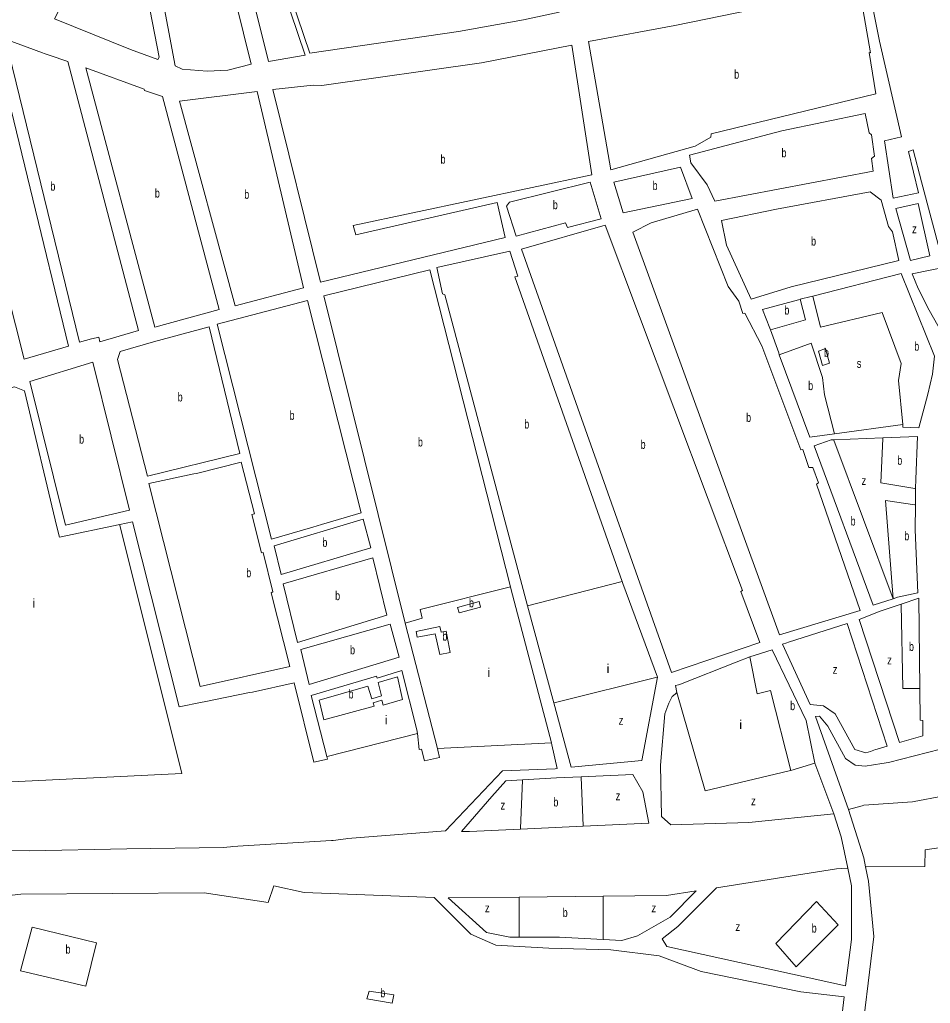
# Model space of a CAD drawing. Extents: x 639657 to 671642, y 222838 to 252123.
# Drawn here: x 642652 to 643678, y 234105 to 235214 of the extents above; entities that cross this region are included whole.
import ezdxf

# ---------------------------------------------------------------- set-up
doc = ezdxf.new("R2010")
doc.units = 0
doc.header["$LTSCALE"] = 4
doc.layers.add('1', color=7, linetype='Continuous', lineweight=13)
doc.layers.add('21', color=7, linetype='Continuous', lineweight=13)
doc.layers.add('7', color=7, linetype='Continuous')

msp = doc.modelspace()

# ---------------------------------------------------------------- linework, layer by layer
at = {"layer": '1'}
for p, q in [((642679.704, 235175.925), (642684.992, 235173.91)), ((643570.344, 234747.002), (643647.326, 234757.379)), ((642848.234, 234702.053), (642851.383, 234702.468)), ((642703.569, 234644.238), (642775.692, 234660.994)), ((642693.955, 234642.004), (642696.839, 234630.37)), ((642778.965, 234647.769), (642831.634, 234439.38)), ((643598.221, 234537.798), (643643.569, 234398.913)), ((643122.747, 234392.465), (643086.25, 234533.693)), ((643518.463, 234512.101), (643584.495, 234533.351)), ((643584.495, 234533.351), (643629.7, 234394.906)), ((643474.826, 234495.531), (643459.398, 234489.597)), ((642855.386, 234462.023), (642956.465, 234484.706)), ((643396.673, 234464.64), (643459.398, 234489.597)), ((642961.146, 234466.215), (642914.438, 234455.926)), ((642910.883, 234455.51), (642859.705, 234444.903)), ((642914.438, 234455.926), (642910.883, 234455.51)), ((643549.039, 234428.282), (643586.076, 234323.444)), ((642998.733, 234380.437), (642998.014, 234383.269)), ((643616.384, 234391.059), (643611.106, 234388.81)), ((643631.069, 234376.7), (643689.772, 234391.725)), ((643108.179, 234378.384), (643125.147, 234382.28)), ((643548.162, 234375.637), (643569.516, 234318.834)), ((643631.069, 234376.7), (643623.852, 234375.548)), ((643131.869, 234299.316), (643021.494, 234290.942)), ((643573.35, 234047.549), (643581.367, 234112.236))]:
    msp.add_line(p, q, dxfattribs=at)
for points in [[(642792.992, 235344.19), (642803.085, 235372.547), (642812.184, 235391.358), (642822.52, 235402.861), (642851.453, 235411.575), (642912.886, 235163.607), (642886.488, 235156.829), (642863.327, 235155.95), (642835.079, 235158.203), (642827.248, 235161.734)], [(642873.517, 235403.517), (642899.409, 235409.278), (642902.966, 235408.882), (642910.604, 235400.985), (642915.534, 235378.154), (642913.124, 235365.76), (642915.814, 235345.055), (642973.841, 235173.995), (642932.486, 235166.609)], [(642709.599, 235251.146), (642717.937, 235248.023), (642722.598, 235253.215), (642743.824, 235299.576), (642759.405, 235327.238), (642772.163, 235345.145), (642775.311, 235345.865), (642809.04, 235171.529), (642807.523, 235168.986), (642776.917, 235180.371), (642691.195, 235214.845)], [(642958.021, 235238.366), (643232.017, 235323.842), (643237.323, 235313.704), (643260.09, 235222.492), (643219.779, 235213.541), (643146.663, 235200.535), (642978.891, 235176.186)], [(643292.982, 235189.183), (643390.264, 235207.133), (643598.223, 235250.179), (643610.993, 235176.605), (643609.265, 235176.701), (643617.095, 235130.323), (643431.389, 235085.108), (643431.093, 235081.554), (643413.44, 235071.451), (643318.311, 235044.471)], [(642620.111, 235201.947), (642706.889, 234845.717), (642657.042, 234831.154), (642560.042, 235213.753), (642561.248, 235219.645)], [(642937.233, 235135.046), (642982.632, 235140.052), (642992.386, 235139.572), (643172.651, 235165.277), (643274.197, 235185.169), (643296.685, 235039.026), (643027.906, 234981.69), (643030.673, 234971.443), (643190.188, 235007.952), (643199.017, 234968.38), (642990.872, 234918.023)], [(642726.475, 235159.41), (642792.362, 235135.64), (642792.772, 235133.915), (642812.903, 235127.171), (642876.959, 234887.028), (642804.164, 234867.322)], [(642832.217, 235122.049), (642919.459, 235132.862), (642971.788, 234911.469), (642894.829, 234891.141)], [(643407.064, 235061.076), (643510.826, 235088.487), (643604.854, 235108.154), (643609.273, 235086.337), (643612.123, 235084.213), (643615.329, 235060.057), (643611.881, 235057.306), (643613.946, 235043.097), (643435.325, 235009.376), (643426.952, 235027.831), (643408.607, 235052.552)], [(643321.594, 235030.672), (643396.732, 235047.745), (643409.819, 235012.449), (643332.241, 234995.978)], [(643200.561, 235003.515), (643204.207, 235008.094), (643295.079, 235030.696), (643307.265, 234989.408), (643269.496, 234979.55), (643267.298, 234984.849), (643211.51, 234969.736)], [(643442.996, 234987.569), (643505.14, 235000.238), (643610.547, 235019.633), (643623.064, 235010.532), (643631.261, 234980.806), (643635.846, 234974.728), (643642.931, 234942.562), (643521.599, 234912.562), (643476.423, 234898.825), (643448.445, 234959.765)], [(643639.438, 235001.064), (643664.807, 235006.502), (643677.962, 234947.715), (643656.037, 234942.451)], [(643343.06, 234974.485), (643363.862, 234984.8), (643415.841, 235000.385), (643450.586, 234913.167), (643462.409, 234896.449), (643467.114, 234882.755), (643469.45, 234883.067), (643488.433, 234846.164), (643532.39, 234729.123), (643534.523, 234729.332), (643541.276, 234708.944), (643545.949, 234708.957), (643552.492, 234691.614), (643550.158, 234690.389), (643599.357, 234547.777), (643508.191, 234520.605)], [(643217.437, 234955.031), (643311.752, 234982.212), (643466.524, 234570.235), (643464.901, 234569.316), (643486.268, 234511.606), (643386.584, 234477.912)], [(642987.237, 234643.366), (642982.237, 234641.901), (642935.775, 234628.29), (642874.643, 234870.745), (642976.291, 234897.369), (643036.993, 234658.029), (642992.237, 234644.722)], [(642765.318, 234839.998), (642802.577, 234850.869), (642865.321, 234867.601), (642900.094, 234724.846), (642795.819, 234699.463), (642762.089, 234830.749)], [(642938.638, 234620.582), (643039.245, 234650.725), (643047.752, 234618.463), (642946.535, 234588.622)], [(642948.795, 234577.967), (643049.912, 234607.199), (643065.912, 234542.467), (642964.899, 234511.916)], [(642968.677, 234503.805), (643069.49, 234532.629), (643079.636, 234495.091), (642978.319, 234464.336)], [(642989.637, 234446.702), (643044.357, 234462.701), (643048.963, 234448.195), (643059.724, 234451.577), (643055.947, 234466.569), (643077.655, 234472.951), (643083.607, 234447.484), (643061.779, 234441.328), (643060.039, 234446.907), (643050.434, 234443.917), (643051.407, 234439.872), (642994.87, 234424.482)]]:
    msp.add_lwpolyline(points, close=True, dxfattribs=at)
for points in [[(643668.427, 235031.072), (643658.895, 235067.19), (643653.922, 235065.145), (643665.002, 235018.777), (643636.57, 235012.703), (643626.565, 235077.452), (643645.755, 235081.874), (643621.121, 235189.732), (643609.196, 235250.008)], [(642734.807, 234854.53), (642732.807, 234853.975), (642719.273, 234850.22), (642635.982, 235192.043), (642677.704, 235176.662), (642679.704, 235175.925)], [(642684.992, 235173.91), (642706.241, 235166.661), (642785.987, 234863.614), (642742.434, 234850.897), (642741.159, 234855.799)], [(643759.519, 235053.001), (643754.458, 234994.974), (643750.463, 234965.72), (643690.055, 234948.995), (643668.427, 235031.072)], [(643331.18, 234580.4), (643209.89, 234923.838), (643213.342, 234924.762), (643204.438, 234952.962), (643122.293, 234934.549), (643128.356, 234904.919), (643131, 234903.708), (643224.471, 234553.082)], [(643825.915, 234873.936), (643823.915, 234873.513), (643819.661, 234872.613), (643807.456, 234922.227), (643750.58, 234915.36), (643731.775, 234920.078), (643739.344, 234941.726), (643735.175, 234943.136), (643657.791, 234927.535), (643664.807, 234910.864), (643677.085, 234886.296), (643699.887, 234845.935), (643717.057, 234827.982)], [(643205.017, 234574.55), (643114.071, 234931.784), (642994.667, 234902.601), (643086.25, 234533.693)], [(643546.006, 234902.175), (643645.404, 234927.847), (643682.906, 234834.648), (643680.718, 234814.436), (643675.692, 234791.678), (643665.52, 234753.675), (643647.435, 234754.435), (643647.326, 234757.379)], [(643498.245, 234864.265), (643497.469, 234866.265), (643489.353, 234887.186), (643529.768, 234898.137), (643531.768, 234898.679)], [(643531.768, 234898.679), (643544.006, 234901.684), (643546.006, 234902.175)], [(643508.165, 234836.17), (643507.459, 234838.17), (643498.245, 234864.265)], [(642741.159, 234855.799), (642739.508, 234855.469), (642734.807, 234854.53)], [(642775.692, 234660.994), (642734.26, 234827.622), (642663.4, 234805.891), (642703.569, 234644.238)], [(643570.344, 234747.002), (643542.415, 234743.367), (643508.165, 234836.17)], [(642589.085, 234784.149), (642646.244, 234800.155), (642657.329, 234795.415), (642693.955, 234642.004)], [(645027.741, 234783.832), (644647.049, 234601.79), (644568.712, 234562.654), (644534.803, 234547.02), (644287.268, 234440.965), (643791.734, 234295.819), (643672.568, 234278.225), (643672.232, 234259.476), (643605.918, 234259.012), (643605.418, 234259.008)], [(643547.517, 234733.533), (643566.499, 234740.289), (643569.482, 234740.397), (643624.688, 234742.399)], [(643624.688, 234742.399), (643663.917, 234743.822), (643661.895, 234696.095), (643661.768, 234685.434), (643661.547, 234666.827)], [(643636.34, 234561.096), (643613.769, 234553.809), (643547.517, 234733.533)], [(642851.383, 234702.468), (642901.743, 234714.9), (642916.609, 234656.866), (642913.462, 234656.045), (642924.331, 234612.925), (642926.464, 234613.236), (642937.438, 234568.898), (642935.409, 234567.877), (642956.465, 234484.706)], [(642855.386, 234462.023), (642797.668, 234690.838), (642848.234, 234702.053)], [(643661.547, 234666.827), (643661.216, 234638.93), (643664.227, 234567.866), (643641.381, 234562.723), (643636.34, 234561.096)], [(642696.839, 234630.37), (642764.631, 234644.732), (642778.965, 234647.769)], [(643205.017, 234574.55), (643205.545, 234572.55), (643251.449, 234398.526)], [(643331.18, 234580.4), (643331.918, 234578.4), (643370.849, 234472.891)], [(643645.468, 234555.037), (643665.257, 234561.878), (643666.626, 234459.869)], [(643370.849, 234472.891), (643353.189, 234378.718), (643273.355, 234371.378), (643253.858, 234443.848), (643224.471, 234553.082)], [(643598.221, 234537.798), (643622.014, 234546.929), (643645.468, 234555.037)], [(643542.941, 234441.937), (643511.67, 234510.056), (643516.463, 234511.499), (643518.463, 234512.101)], [(643474.826, 234495.531), (643500.002, 234503.523), (643538.59, 234423.932), (643548.162, 234375.637)], [(642998.014, 234383.269), (642980.583, 234451.956), (643053.983, 234473.796), (643054.902, 234471.768), (643082.82, 234480.277), (643099.637, 234413.314)], [(642998.733, 234380.437), (642983.378, 234376.859), (642961.146, 234466.215)], [(643392.63, 234455.389), (643391.131, 234463.213), (643394.673, 234464.125), (643396.673, 234464.64)], [(643392.63, 234455.389), (643390.63, 234453.65), (643387.358, 234450.805), (643383.515, 234443.483), (643379.175, 234431.286), (643374.332, 234373.601)], [(643666.626, 234459.869), (643667.102, 234424.408), (643669.744, 234423.908), (643669.988, 234406.546), (643643.569, 234398.913)], [(642859.705, 234444.903), (642857.705, 234444.509), (642831.634, 234439.38)], [(643611.106, 234388.81), (643605.522, 234387.271), (643593.12, 234390.991), (643571.183, 234431.236), (643557.809, 234440.566), (643542.941, 234441.937)], [(643593.567, 234373.427), (643582.678, 234381.214), (643562.987, 234417.404), (643553.489, 234428.605), (643549.039, 234428.282)], [(643108.179, 234378.384), (643104.767, 234391.601), (643102.33, 234391.086), (643100.143, 234409.135), (643099.637, 234413.314)], [(643251.449, 234398.526), (643251.875, 234396.526), (643257.612, 234369.607)], [(643629.7, 234394.906), (643618.384, 234391.637), (643616.384, 234391.059)], [(643122.747, 234392.465), (643123.218, 234390.465), (643125.147, 234382.28)], [(643374.332, 234373.601), (643375.381, 234315.832), (643385.766, 234306.42), (643473.636, 234309.011), (643569.516, 234318.834)], [(643623.852, 234375.548), (643605.049, 234372.547), (643593.567, 234373.427)], [(643131.869, 234299.316), (643196.054, 234367.194), (643255.612, 234369.529), (643257.612, 234369.607)], [(643218.639, 234357.045), (643256.997, 234359.406), (643284.685, 234360.537)], [(643284.685, 234360.537), (643342.943, 234362.916), (643354.344, 234343.613), (643361.251, 234308.073)], [(643216.324, 234301.483), (643158.772, 234298.865), (643150.002, 234298.865), (643184.205, 234338.348), (643199.991, 234355.897), (643218.639, 234357.045)], [(643660.104, 234332.5), (643692.02, 234338.612), (643694.02, 234338.995)], [(643586.076, 234323.444), (643601.425, 234327.717), (643603.425, 234328.274)], [(643603.425, 234328.274), (643658.104, 234332.351), (643660.104, 234332.5)], [(643585.296, 234257.257), (643577.981, 234292.723), (643569.516, 234318.834)], [(643586.076, 234323.444), (643603.414, 234269.032), (643605.418, 234259.008)], [(643361.251, 234308.073), (643287.011, 234304.697), (643216.324, 234301.483)], [(642891.599, 234281.802), (643003.347, 234288.441), (643005.347, 234288.56)], [(643021.494, 234290.942), (643019.494, 234290.647), (643005.347, 234288.56)], [(642881.423, 234280.787), (642772.52, 234279.353), (642662.503, 234276.799), (642591.792, 234278.015), (642391.857, 234279.058), (642034.894, 234276.516)], [(642881.423, 234280.787), (642889.599, 234281.603), (642891.599, 234281.802)], [(643585.296, 234257.257), (643584.796, 234257.226), (643572.505, 234256.476), (643437.364, 234235.396)], [(643582.906, 234124.647), (643589.382, 234176.904), (643589.382, 234237.445), (643585.296, 234257.257)], [(643605.418, 234259.008), (643608.676, 234242.71), (643614.815, 234180.413), (643598.392, 234047.419)], [(643119.12, 234224.471), (642972.745, 234230.146), (642938.301, 234237.503), (642932.19, 234218.865), (642859.711, 234229.772), (642653.107, 234227.915), (642617.407, 234224.107), (642056.301, 234221.39), (642032.886, 234208.556), (642007.734, 234217.783), (641601.897, 234217.647)], [(643414.508, 234231.832), (643380.893, 234226.588), (643309.617, 234225.809), (643214.9, 234224.773), (643134.874, 234223.898)], [(643309.617, 234177.08), (643330.665, 234176.027), (643348.205, 234181.291), (643385.039, 234202.349), (643414.508, 234231.832)], [(643437.364, 234235.396), (643393.809, 234191.82), (643376.269, 234177.781), (643381.531, 234169.007), (643582.906, 234124.647)], [(643581.367, 234112.236), (643532.376, 234118.117), (643420.119, 234140.93), (643372.761, 234158.478), (643318.387, 234165.498), (643248.226, 234167.253), (643188.59, 234170.762), (643160.526, 234183.046), (643119.12, 234224.471)], [(643134.874, 234223.898), (643178.066, 234184.801), (643204.376, 234179.536), (643214.9, 234179.536)], [(643214.9, 234179.536), (643260.504, 234179.536), (643309.617, 234177.08)]]:
    msp.add_lwpolyline(points, dxfattribs=at)
at = {"layer": '21'}
for p, q in [((643224.471, 234553.082), (643331.18, 234580.4)), ((643424.484, 234344.607), (643392.63, 234455.389)), ((643251.449, 234398.526), (643122.747, 234392.465)), ((643548.162, 234375.637), (643521.146, 234367.632))]:
    msp.add_line(p, q, dxfattribs=at)
for points in [[(643498.245, 234864.265), (643537.636, 234875.549), (643531.768, 234898.679)], [(643647.326, 234757.379), (643642.435, 234807.014), (643645.438, 234826.416), (643624.173, 234883.619), (643554.621, 234867.374), (643546.006, 234902.175)], [(643508.165, 234836.17), (643543.996, 234849.27), (643556.684, 234810.521), (643559.168, 234791.034), (643570.344, 234747.002)], [(643569.482, 234740.397), (643569.668, 234739.897), (643636.34, 234561.096)], [(643661.768, 234685.434), (643660.946, 234685.571), (643622.71, 234691.947), (643624.668, 234741.899), (643624.688, 234742.399)], [(643636.34, 234561.096), (643627.972, 234671.767), (643661.047, 234666.901), (643661.547, 234666.827)], [(642764.631, 234644.732), (642764.756, 234644.232), (642834.724, 234364.233), (642611.792, 234353.353), (642611.292, 234353.329)], [(643086.25, 234533.693), (643105.641, 234539.232), (643103.486, 234548.872), (643205.017, 234574.55)], [(643645.468, 234555.037), (643645.477, 234554.537), (643647.263, 234459.869), (643666.126, 234459.869), (643666.626, 234459.869)], [(643521.146, 234367.632), (643498.179, 234457.625), (643483.355, 234453.825), (643474.826, 234495.531)], [(643370.849, 234472.891), (643370.349, 234472.767), (643258.858, 234445.089), (643253.858, 234443.848)], [(643100.143, 234409.135), (642998.514, 234383.396), (642998.014, 234383.269)], [(643284.685, 234360.537), (643284.706, 234360.037), (643286.99, 234305.197), (643287.011, 234304.697)], [(643521.146, 234367.632), (643519.146, 234367.156), (643424.484, 234344.607)], [(643218.639, 234357.045), (643218.618, 234356.545), (643216.345, 234301.982), (643216.324, 234301.483)], [(643214.9, 234224.773), (643214.9, 234224.273), (643214.9, 234180.036), (643214.9, 234179.536)], [(643309.617, 234225.809), (643309.617, 234225.309), (643309.617, 234177.58), (643309.617, 234177.08)]]:
    msp.add_lwpolyline(points, dxfattribs=at)
for points in [[(643552.246, 234840.359), (643560.367, 234843.023), (643564.672, 234826.587), (643556.779, 234824.201)], [(643145.437, 234551.43), (643169.789, 234557.864), (643171.342, 234551.607), (643147.179, 234545.14)], [(643098.938, 234524.321), (643125.576, 234529.645), (643126.82, 234523.481), (643132.801, 234524.386), (643137.123, 234500.64), (643125.548, 234498.271), (643120.334, 234521.539), (643099.901, 234517.69)], [(643574.529, 234193.631), (643549.916, 234219.897), (643504.312, 234172.517), (643527.114, 234146.195)], [(642665.985, 234191.027), (642652.739, 234141.807), (642726.408, 234124.259), (642738.686, 234173.394)], [(643045.669, 234118.609), (643073.515, 234114.527), (643071.708, 234105.079), (643043.353, 234109.972)]]:
    msp.add_lwpolyline(points, close=True, dxfattribs=at)

# ---------------------------------------------------------------- texts
at = {"layer": '7'}
for s, width, p in [('b', 0.75, (643457.266, 235147.325)), ('b', 0.75, (643126.305, 235051.596)), ('b', 0.75, (643510.596, 235058.765)), ('b', 0.75, (642686.53, 235021.131)), ('b', 0.75, (643365.314, 235021.861)), ('b', 0.75, (642804.289, 235013.366)), ('b', 0.75, (642905.042, 235012.001)), ('b', 0.75, (643252.853, 235000.216)), ('z', 0.8, (643657.791, 234973.16)), ('b', 0.75, (643543.975, 234959.229)), ('b', 0.75, (643513.852, 234881.472)), ('b', 0.75, (643660.276, 234840.761)), ('b', 0.75, (643558.485, 234833.612)), ('s', 0.8, (643595.4, 234821.435)), ('b', 0.75, (643540.684, 234796.318)), ('b', 0.75, (642830.009, 234783.532)), ('b', 0.75, (642956.133, 234762.829)), ('b', 0.75, (643470.761, 234760.495)), ('b', 0.75, (643220.693, 234753.022)), ('b', 0.75, (642718.922, 234735.93)), ('b', 0.75, (643100.791, 234732.738)), ('b', 0.75, (643351.836, 234730.062)), ('b', 0.75, (643641.127, 234712.128)), ('z', 0.8, (643600.785, 234689.315)), ('b', 0.75, (643588.507, 234643.689)), ('b', 0.75, (642993.148, 234619.673)), ('b', 0.75, (643649.02, 234627.018)), ('b', 0.75, (642907.336, 234585.413)), ('b', 0.75, (643007.486, 234559.557)), ('b', 0.75, (643158.33, 234551.502)), ('b', 0.75, (643128.366, 234513.958)), ('b', 0.75, (643024.348, 234498.482)), ('b', 0.75, (643654.3, 234502.303)), ('z', 0.8, (643629.723, 234487.069)), ('z', 0.8, (643568.333, 234476.54)), ('b', 0.75, (643022.661, 234448.716)), ('b', 0.75, (643520.355, 234435.577)), ('z', 0.8, (643327.081, 234419.121)), ('z', 0.8, (643323.649, 234333.962)), ('z', 0.8, (643193.852, 234323.433)), ('b', 0.75, (643253.488, 234326.942)), ('z', 0.8, (643476.248, 234328.258)), ('z', 0.8, (643176.312, 234207.614)), ('b', 0.75, (643264.012, 234202.349)), ('z', 0.8, (643363.991, 234207.614)), ('z', 0.8, (643458.708, 234186.556)), ('b', 0.75, (643544.654, 234184.801)), ('b', 0.75, (642703.606, 234161.11)), ('b', 0.75, (643058.428, 234111.844))]:
    msp.add_text(s, height=10, dxfattribs=dict(at, width=width)).set_placement(p)
for p in [(642666.339, 234551.125), (643179.385, 234473.032), (643313.567, 234477.419), (643063.62, 234419.51), (643463.093, 234414.244)]:
    msp.add_text('i', height=10, dxfattribs=at).set_placement(p)

doc.saveas('drawing.dxf')
